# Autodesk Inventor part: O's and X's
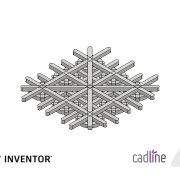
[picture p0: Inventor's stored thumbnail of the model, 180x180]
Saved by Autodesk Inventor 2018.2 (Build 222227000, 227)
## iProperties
Created: 2018-03
Part Number: O's and X's
Material: Generic
Document SubType Name: Modeling
Designer: PeterMaxwell-Stewart
Mass: 73.9673 g
Surface Area: 597.02 cm^2
Volume: 73.9673 cm^3
Density: 1 g/cm^3
Appearance: Default
Author: PeterMaxwell-Stewart
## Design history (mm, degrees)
sketch "Sketch3"
  geometry: C1 r 15 at (0, 0); C2 r 10 at (0, 0); 1 further point
  constraints: 2 centre point, 1 coincident
  dimensions: "d0" = 30 diameter of C1; "d1" = 5 radial gap between concentric circles of C1 C2
extrude "Extrusion1" new body sketch "Sketch3" distance "d2" = 5; taper "d3" = 0 deg
sketch "Sketch4"
  geometry: L1 (-10.607, -10.607)-(10.607, 10.607); L2 (-8.839, -12.374)-(12.374, 8.839); L3 (8.839, 12.374)-(-12.374, -8.839); L4 (0, 0)-(30, 0); L5 (-10.607, 10.607)-(10.607, -10.607); L6 (-12.374, 8.839)-(8.839, -12.374); L7 (12.374, -8.839)-(-8.839, 12.374); L8 (0, 0)-(30, 0); A1 r 2.5 centre (-10.607, -10.607) between (-12.374, -8.839) and (-8.839, -12.374); A2 r 2.5 centre (10.607, 10.607) between (12.374, 8.839) and (8.839, 12.374); A3 r 2.5 centre (-10.607, 10.607) between (-8.839, 12.374) and (-12.374, 8.839); A4 r 2.5 centre (10.607, -10.607) between (8.839, -12.374) and (12.374, -8.839)
  constraints: 20 end point, 8 point on circle, 8 tangent, 4 centre point, 2 equal length, 2 horizontal, 2 midpoint, 2 parallel
  dimensions: "d4" = 15 distance of L4.start L1.end; "d5" = 45 deg angle of L4 L1; "d6" = 5 diameter of A2; "d7" = 15 distance of L4.start L5.end; "d8" = 45 deg angle of L5 L8; "d9" = 5 diameter of A4
extrude "Extrusion2" new body sketch "Sketch4" distance "d10" = 5; taper "d11" = 0 deg
pattern_linear "Rectangular Pattern1"
sketch "Sketch5"
  geometry: L1 (20, -65)-(20, 65); L2 (22.5, -65)-(22.5, 65); L3 (17.5, 65)-(17.5, -65); L4 (-20, -65)-(-20, 65); L5 (-17.5, -65)-(-17.5, 65); L6 (-22.5, 65)-(-22.5, -65); L7 (-65, 20)-(65, 20); L8 (-65, 17.5)-(65, 17.5); L9 (65, 22.5)-(-65, 22.5); L10 (-65, -20)-(65, -20); L11 (-65, -22.5)-(65, -22.5); L12 (65, -17.5)-(-65, -17.5); A1 r 2.5 centre (20, -65) between (17.5, -65) and (22.5, -65); A2 r 2.5 centre (20, 65) between (22.5, 65) and (17.5, 65); A3 r 2.5 centre (-20, -65) between (-22.5, -65) and (-17.5, -65); A4 r 2.5 centre (-20, 65) between (-17.5, 65) and (-22.5, 65); A5 r 2.5 centre (-65, 20) between (-65, 22.5) and (-65, 17.5); A6 r 2.5 centre (65, 20) between (65, 17.5) and (65, 22.5); A7 r 2.5 centre (-65, -20) between (-65, -17.5) and (-65, -22.5); A8 r 2.5 centre (65, -20) between (65, -22.5) and (65, -17.5); 5 further points
  constraints: 32 end point, 16 point on circle, 16 tangent, 8 centre point, 6 parallel, 4 midpoint, 3 equal length, 2 horizontal alignment, 2 vertical alignment, 1 perpendicular, 1 vertical
  dimensions: "FrameLength" = 65 distance of point (20, 0) L1.end; "Thickness" = 5 diameter of A2; "d20" = 5 diameter of A4 (= Thickness); "d21" = 5 diameter of A6 (= Thickness); "d22" = 5 diameter of A8 (= Thickness); "d23" = 40 distance between parallel lines of L1 L4; "d24" = 40 distance between parallel lines of L10 L7; "d25" = 20 distance from line of point (0, 0) L7 (= 0.5 x d23); "d26" = 20 distance from line of point (0, 0) L1 (= d25)
extrude "Extrusion3" new body sketch "Sketch5" distance "d27" = 5; taper "d28" = 0 deg
sketch "Sketch6"
  geometry: L1 (-65, 0)-(65, 0); L2 (-65, -2.5)-(65, -2.5); L3 (65, 2.5)-(-65, 2.5); L4 (0, -71.504)-(0, 71.504); L5 (2.5, -71.504)-(2.5, 71.504); L6 (-2.5, 71.504)-(-2.5, -71.504); L7 (-56.569, -56.569)-(56.569, 56.569); L8 (-54.801, -58.336)-(58.336, 54.801); L9 (54.801, 58.336)-(-58.336, -54.801); L10 (0, 0)-(160, 0); C1 r 10 at (0, 0) reference; A1 r 2.5 centre (-65, 0) between (-65, 2.5) and (-65, -2.5); A2 r 2.5 centre (65, 0) between (65, -2.5) and (65, 2.5); A3 r 2.5 centre (0, -71.504) between (-2.5, -71.504) and (2.5, -71.504); A4 r 2.5 centre (0, 71.504) between (2.5, 71.504) and (-2.5, 71.504); A5 r 2.5 centre (-56.569, -56.569) between (-58.336, -54.801) and (-54.801, -58.336); A6 r 2.5 centre (56.569, 56.569) between (58.336, 54.801) and (54.801, 58.336); 1 further point
  constraints: 26 end point, 12 point on circle, 12 tangent, 6 centre point, 3 midpoint, 3 parallel, 2 horizontal, 1 equal length, 1 perpendicular
  dimensions: "d29" = 5 diameter of A2; "d30" = 130 distance of L1.start L1.end; "d31" = 5 diameter of A4; "d32" = 80 distance of L10.start L7.end; "d33" = 45 deg angle of L10 L7; "d34" = 5 diameter of A6
extrude "Extrusion4" new body sketch "Sketch6" distance "d35" = 5; taper "d36" = 0 deg
extrude "Extrusion5" new body sketch "Sketch6" distance "d37" = 5; taper "d38" = 0 deg
extrude "Extrusion6" new body sketch "Sketch6" distance "d39" = 5; taper "d40" = 0 deg
pattern_linear "Rectangular Pattern2"
pattern_linear "Rectangular Pattern3"
mirror "Mirror1"
node "Mid Centre O"
node "Mid Centre X"
feature "Pattern of Mid Centre X:1"
node "Top Centre X"
feature "Pattern of Mid Centre X:2"
node "Bottom Centre X"
feature "Pattern of Mid Centre X:3"
node "Mid Right X"
feature "Pattern of Mid Centre X:4"
node "Top Right X"
feature "Pattern of Mid Centre X:5"
node "Bottom Right X"
feature "Pattern of Mid Centre X:6"
node "Mid Left X"
feature "Pattern of Mid Centre X:7"
node "Top Left X"
feature "Pattern of Mid Centre X:8"
node "Bottom Left X"
feature "Pattern of Mid Centre O:9"
node "Top centre O"
feature "Pattern of Mid Centre O:10"
node "Bottom Centre O"
feature "Pattern of Mid Centre O:11"
node "Mid Right O"
feature "Pattern of Mid Centre O:12"
node "Top Right O"
feature "Pattern of Mid Centre O:13"
node "Bottom Right O"
feature "Pattern of Mid Centre O:14"
node "Mid Left O"
feature "Pattern of Mid Centre O:15"
node "Top Left O"
feature "Pattern of Mid Centre O:16"
node "Bottom Left O"
node "Frame"
node "Central Win"
node "Mid Win"
node "Diagonal Up Win"
feature "Pattern of Diagonal Up Win:17"
node "Top Win"
feature "Pattern of Diagonal Up Win:18"
node "Bottom Win"
feature "Pattern of Diagonal Up Win:19"
node "Right Win"
feature "Pattern of Diagonal Up Win:20"
node "Left Win"
feature "Pattern of Diagonal Up Win:21"
node "Diagonal Down Win"
